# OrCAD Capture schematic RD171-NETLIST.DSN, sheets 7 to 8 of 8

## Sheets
7 2: size Custom
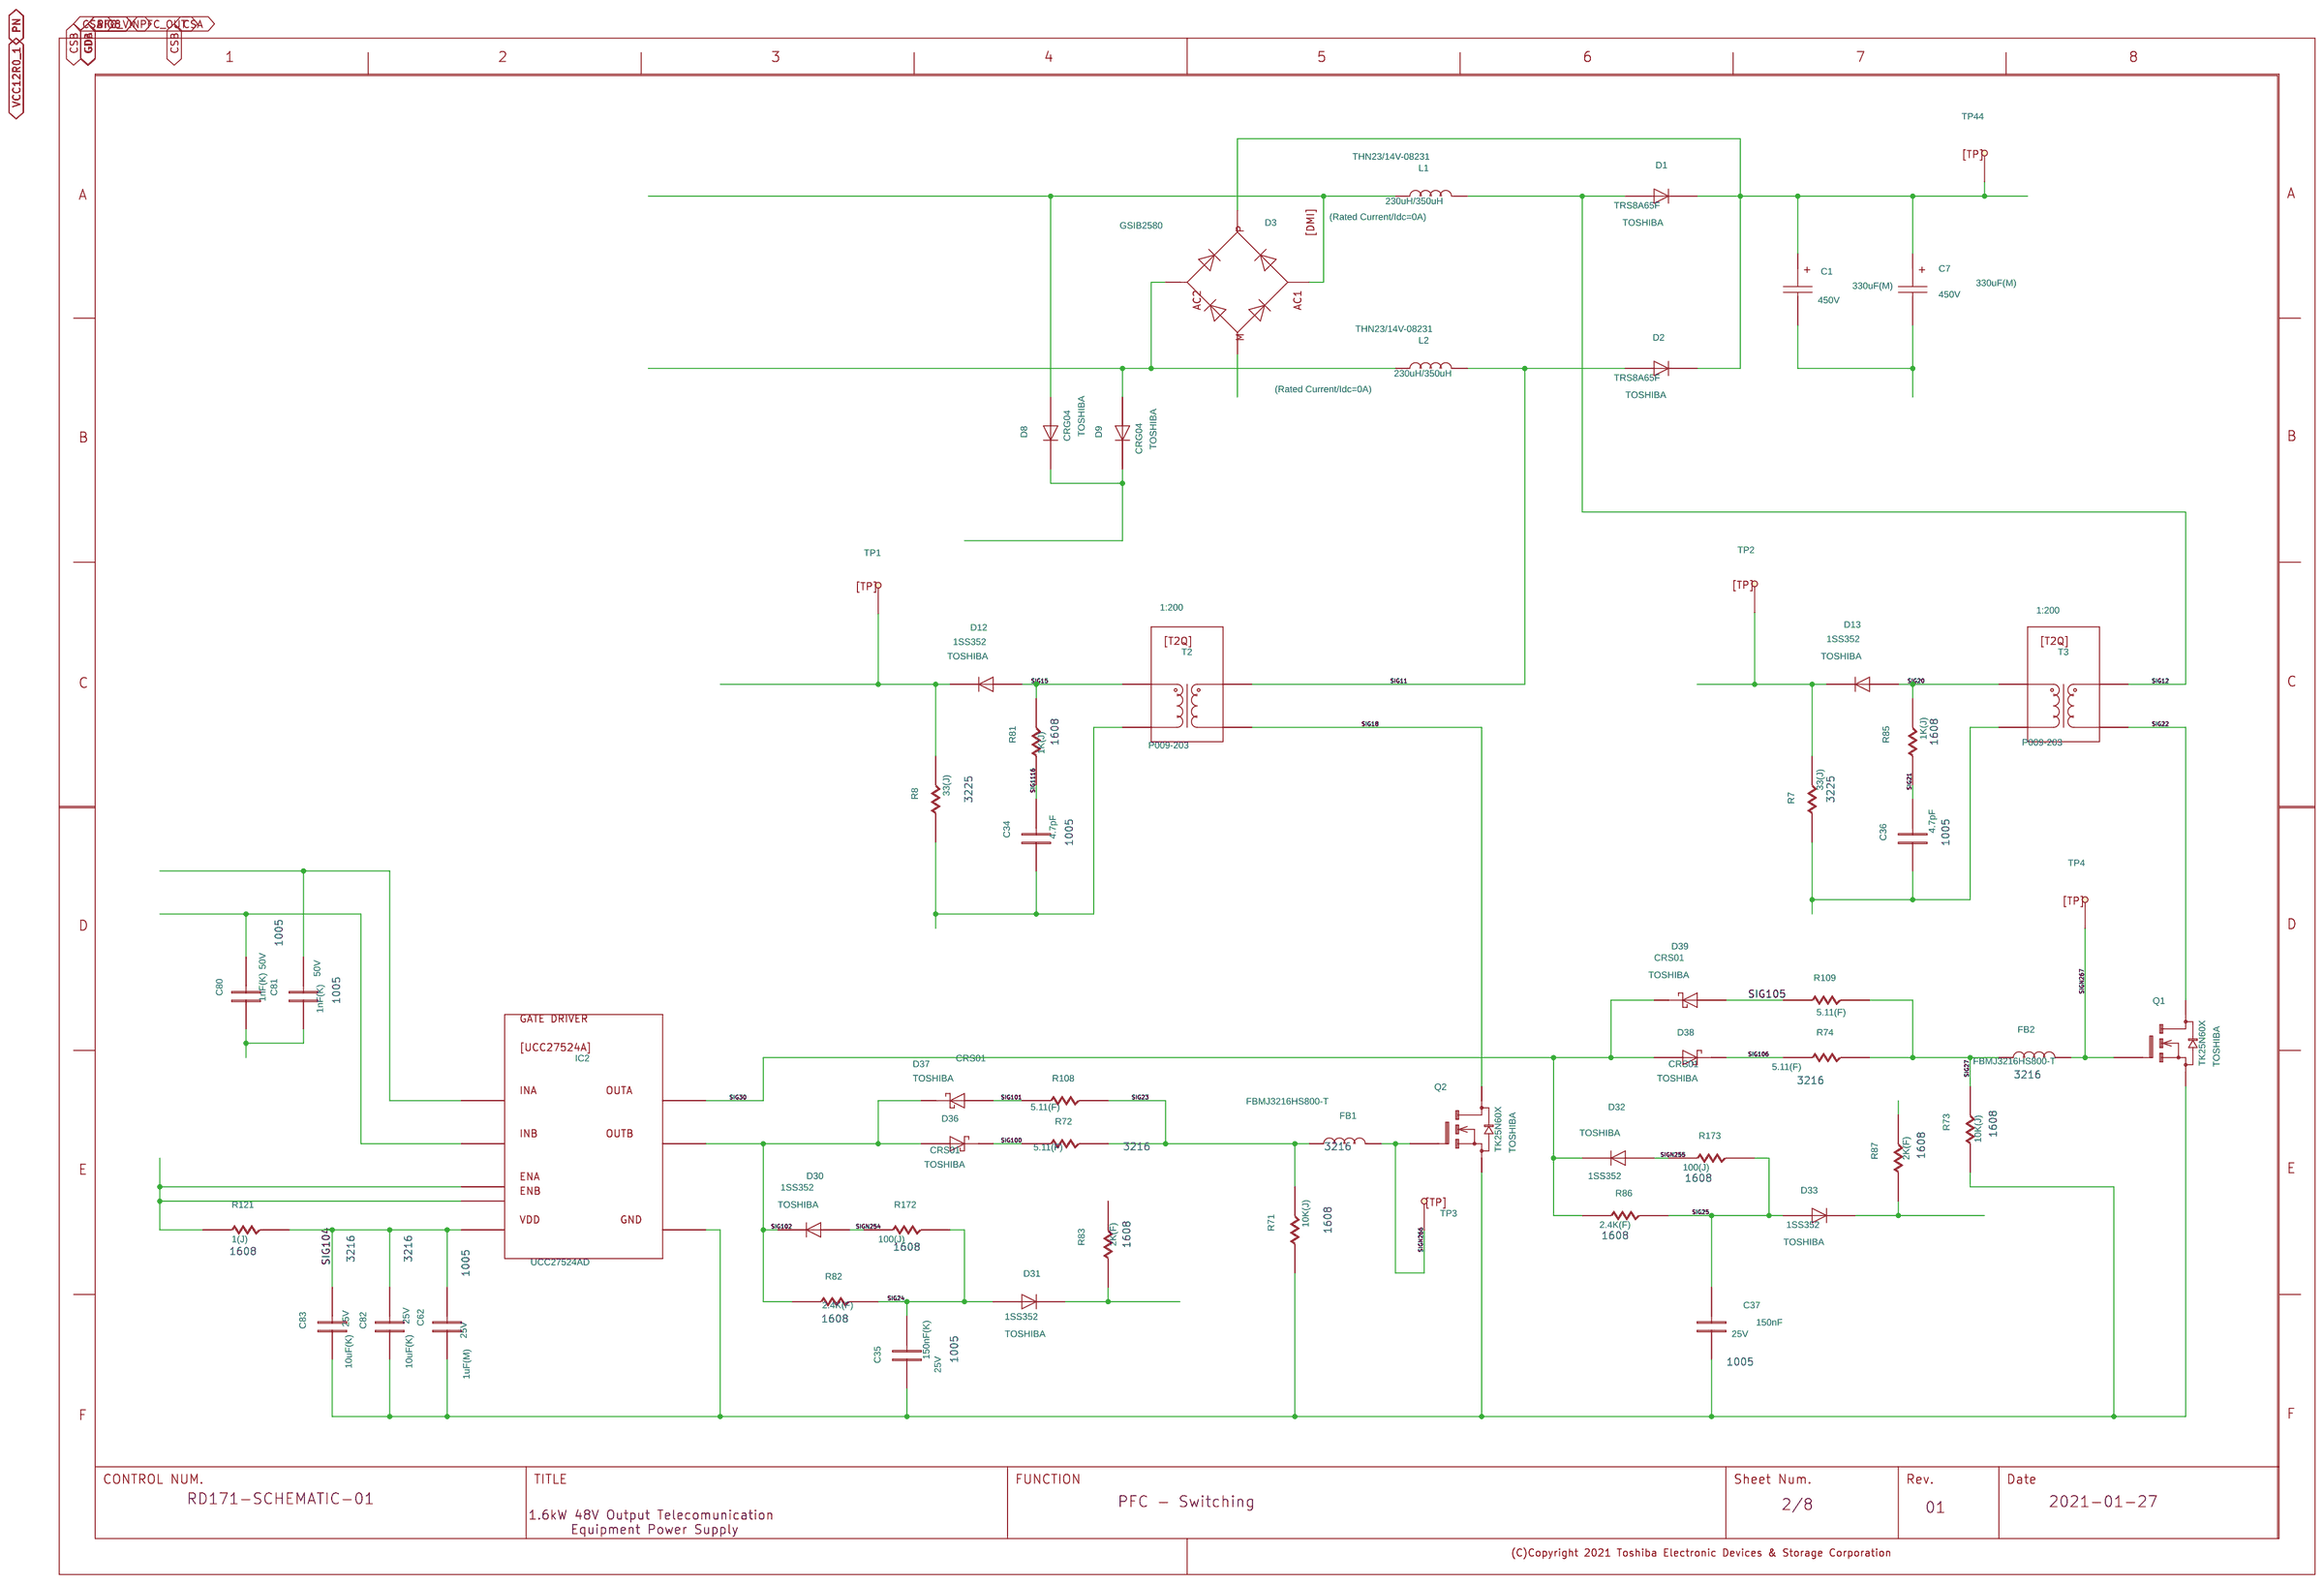
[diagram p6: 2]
8 1: size A3
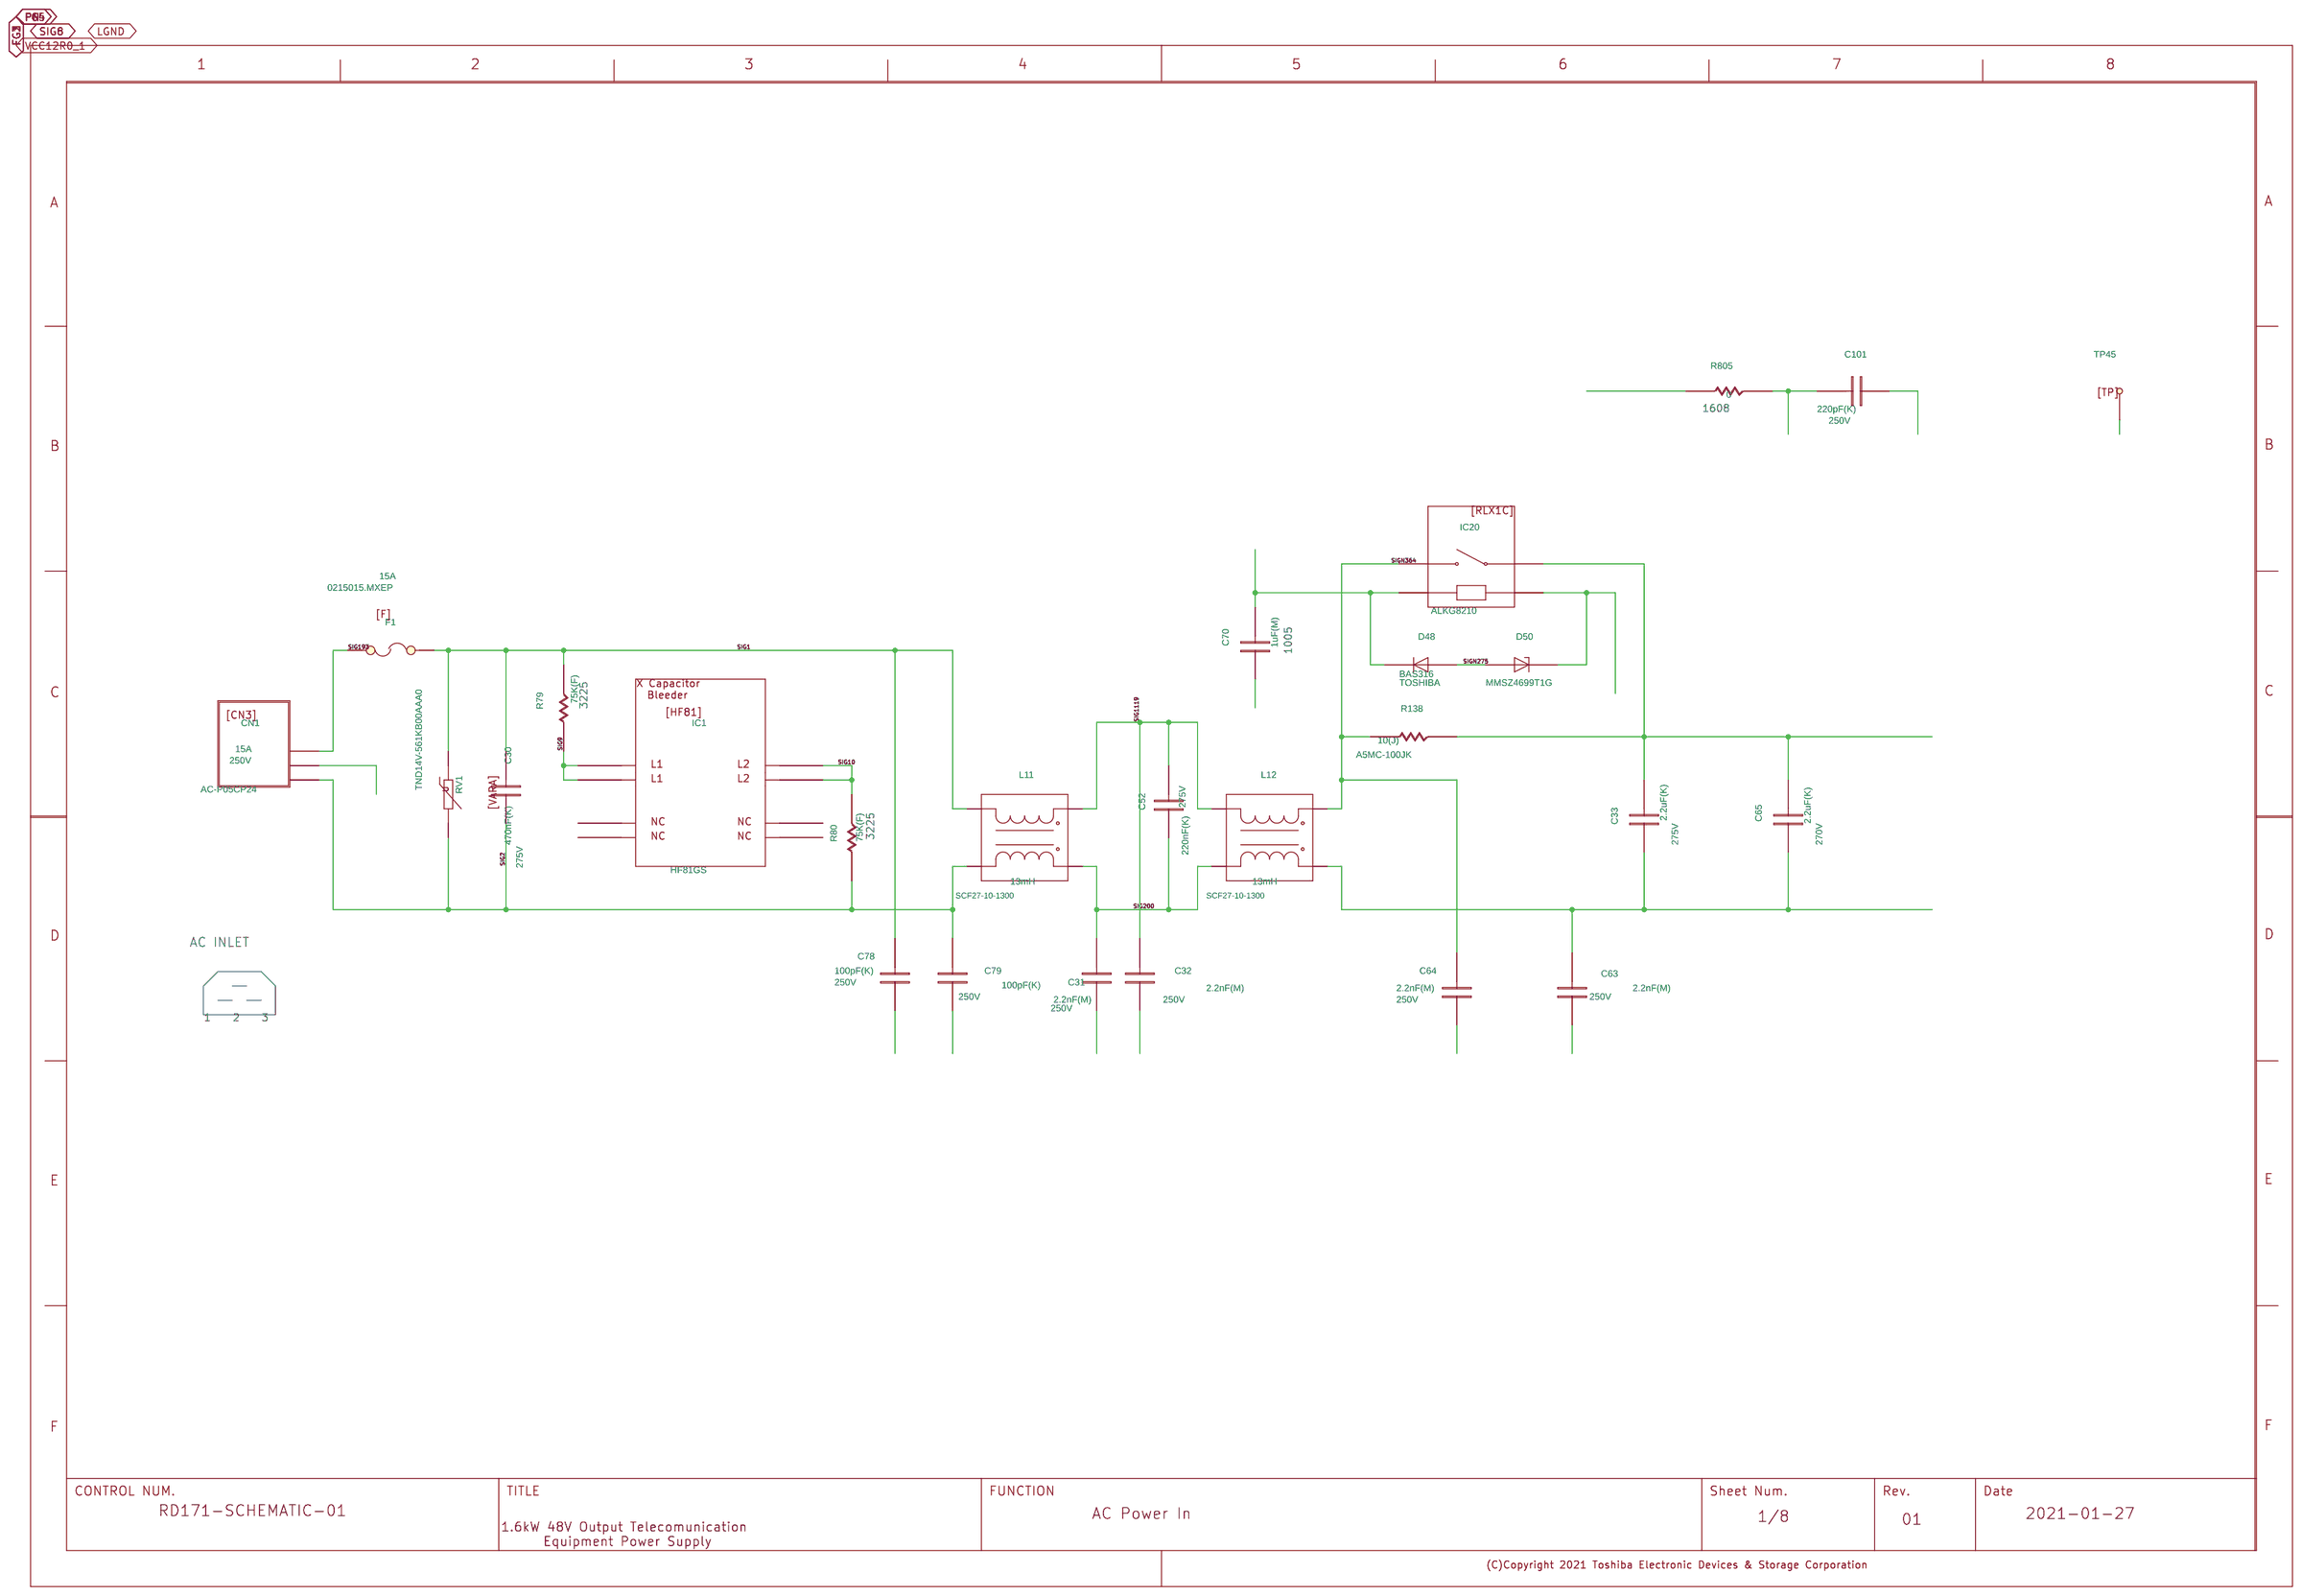
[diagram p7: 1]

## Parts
sheet 1
C30  470nF  [LE474-M]
C31  2.2nF  [DE2E3KY222MN3AM02F]
C32  2.2nF  [DE2E3KY222MN3AM02F]
C33  2.2uF  [890324026034CS]
C52  220nF  [LE224-M]
C63  2.2nF  [DE2E3KY222MN3AM02F]
C64  2.2nF  [DE2E3KY222MN3AM02F]
C65  2.2uF  [890324026034CS]
C70  1uF
C78  100pF  [DE2B3KY101KA3BM02F]
C79  100pF  [DE2B3KY101KA3BM02F]
C101  220pF  [DE2B3KY221KA3BM02F]
CN1  15A  [AC-P05CP24]
D48  D48  [BAS316]
D50  D50  [MMSZ4699T1G]
F1  15 A  [0215015.MXEP]
IC1  IC1  [HF81GS]
IC20  IC20  [ALKG8210]
L11  13mH  [SCF27-10-1300]
L12  13mH  [SCF27-10-1300]
R79  75k
R80  75k
R138  10_2.1W- FUSE  [A5MC-100JK]
R805  0
RV1  560V  [TND14V-561KB00AAA0]
TP45  TP45  [LC-22-S-WHITE]
U?#7  WAKU_DEF100
sheet 2
C1  330uF  [450MXK330MEFCSN30X30]
C7  330uF  [450MXK330MEFCSN30X30]
C34  4.7pF
C35  150nF  [C1005X5R1E154K050BC]
C36  4.7pF
C37  150nF  [C1005X5R1E154K050BC]
C62  1uF
C80  1nF
C81  1nF
C82  10uF
C83  10uF
D1  D1  [TRS8E65F]
D2  D2  [TRS8E65F]
D3  D3  [GSIB2580]
D8  D8  [CRG04]
D9  D9  [CRG04]
D12  D12  [1SS352]
D13  D13  [1SS352]
D30  D30  [1SS352]
D31  D31  [1SS352]
D32  D32  [1SS352]
D33  D33  [1SS352]
D36  D36  [CRS01]
D37  D37  [CRS01]
D38  D38  [CRS01]
D39  D39  [CRS01]
FB1  FB1  [FBMJ3216HS800-T]
FB2  FB2  [FBMJ3216HS800-T]
IC2  IC2  [UCC27524AD]
L1  230uH/350uH(RatedCurrent/Idc=0)  [THN23/14V-08231]
L2  230uH/350uH (Rated Current/Idc=0)  [THN23/14V-08231]
Q1  Q1  [TK25N60X]
Q2  Q2  [TK25N60X]
R7  33
R8  33
R71  10k
R72  5.11
R73  10k
R74  5.11
R81  1k
R82  2.4k
R83  2k
R85  1k
R86  2.4k
R87  2k
R108  5.11
R109  5.11
R121  1
R172  100
R173  100
T2  1:200  [P009-203]
T3  1:200  [P009-203]
TP1  TP1  [HK-2-S]
TP2  TP2  [HK-2-S]
TP3  TP3  [HK-2-S]
TP4  TP4  [HK-2-S]
TP44  TP44  [HK-2-S]
U?#6  WAKU_DEF100

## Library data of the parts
C30 = C: ADSMODELNAME: s_GRM32MR72A474KA01L; CAPACITANCETOLE: K; COMP: PRT_19; COMPONENTNAME: C_C.Normal_package; FUNCTION: C_C.Normal_package; GCOUNT: 1; INSTANCENAME: INS121; MAKER: OKAYA; MAXGCOUNT: 1; NOMINALCAPACITA: 470n; PARTNAME: LE474-M_OK; RATEDVOLTAGE: 100; SIZECODESMD: 3225; VAL1: 470nF(K); VAL2: 275V
C31 = C: ADSMODELNAME: s_ECKNTS222ME; CAPACITANCETOLE: M; CDMASTERCADCELG: DC0284; CHIPSIZE: [hsb`7.5mmió]; COMP: PRT_13; COMPONENTNAME: C_C.Normal_package; FNLEADFREETHET1GT2GMCTH1: N_N_N; FUNCTION: C_C.Normal_package; GCOUNT: 1; INSTANCENAME: INS259; MAKER: MURATA; MAXGCOUNT: 1; NOMINALCAPACITA: 2.2n; OUMECLASSIFICATION: ƒZƒ‰ƒ~ƒbƒNƒRƒ“ƒfƒ“ƒT; OUMEMAKER: NAE pi\jbNGNgjbNfoCX; OUMEMAKERKATAMEI: ECKNTS222ME; PARTNAME: DE2E3KY222MN3AM02F_MU; PMPRODUCTSTYPEG: ES; QUADMODEL: CON_2.2N; RATEDVOLTAGE: 250; SIZECODESMD: DIP; TEMPCHARACTERI2: E; VAL1: 2.2nF(M); VAL2: 250V
C32 = C: ADSCNVFLAG: ON; ADSMODELNAME: s_ECKNTS222ME; CAPACITANCETOLE: M; CDMASTERCADCELG: DC0284; CHIPSIZE: [hsb`7.5mmió]; COMP: PRT_13; COMPONENTNAME: C_C.Normal_package; FNLEADFREETHET1GT2GMCTH1: N_N_N; FUNCTION: C_C.Normal_package; GCOUNT: 1; ICX_PART_MODEL: CON_2.2N; INSTANCENAME: INS269; MAKER: MURATA; MAXGCOUNT: 1; NOMINALCAPACITA: 2.2n; OUMECLASSIFICATION: ƒZƒ‰ƒ~ƒbƒNƒRƒ“ƒfƒ“ƒT; OUMEMAKER: NAE pi\jbNGNgjbNfoCX; OUMEMAKERKATAMEI: ECKNTS222ME; PARTNAME: DE2E3KY222MN3AM02F_MU; PMPRODUCTSTYPEG: ES; QUADMODEL: CON_2.2N; RATEDVOLTAGE: 250; SIZECODESMD: DIP; SQ_PART_MODEL: CON_2.2N; TEMPCHARACTERI2: E; VAL1: 2.2nF(M); VAL2: 250V
C33 = C: CAPACITANCETOLE: K; CDMASTERCADCELG: DC0511; COMP: PRT_18; COMPONENTNAME: C_C.Normal_package; FNLEADFREETHET1GT2GMCTH1: 9_N_N; FUNCTION: C_C.Normal_package; GCOUNT: 1; INSTANCENAME: INS309; MAKER: Wurth; MAXGCOUNT: 1; NOMINALCAPACITA: 2.2u; OUMECLASSIFICATION: ƒtƒBƒ‹ƒƒRƒ“ƒfƒ“ƒT; OUMEMAKER: CHM “ú–{ƒPƒ~ƒRƒ“; OUMEMAKERKATAMEI: TACB2E225K; PARTNAME: 890324026034CS_WE; QUADMODEL: CON_2.2U; RATEDVOLTAGE: 250; SIZECODESMD: DIP; VAL1: 2.2uF(K); VAL2: 275V
C52 = C: CAPACITANCETOLE: M; COMP: PRT_17; COMPONENTNAME: C_C.Normal_package; FNLEADFREETHET1GT2GMCTH1: N_N_N; FUNCTION: C_C.Normal_package; GCOUNT: 1; INSTANCENAME: INS279; MAKER: OKAYA; MAXGCOUNT: 1; NOMINALCAPACITA: 220n; OUMECLASSIFICATION: ƒtƒBƒ‹ƒƒRƒ“ƒfƒ“ƒT; OUMEMAKER: NIS ƒjƒbƒZƒC“d‹@; OUMEMAKERKATAMEI: R40KI322000**M; PARTNAME: LE224-M_OK; QUADMODEL: CON_220N; RATEDVOLTAGE: 275; SIZECODESMD: DIP; VAL1: 220nF(K); VAL2: 275V
C63 = C: ADSMODELNAME: s_DE2E3KY222MN3AM02F; CAPACITANCETOLE: M; CDMASTERCADCELG: SIK0018; CHIPSIZE: [hsb`7.5mmió]; COMP: PRT_13; COMPONENTNAME: C_C.Normal_package; FNLEADFREETHET1GT2GMCTH1: N_N_N; FUNCTION: C_C.Normal_package; GCOUNT: 1; INSTANCENAME: INS289; MAKER: MURATA; MAXGCOUNT: 1; NOMINALCAPACITA: 2.2n; OUMECLASSIFICATION: ƒZƒ‰ƒ~ƒbƒNƒRƒ“ƒfƒ“ƒT; OUMEMAKER: MRT ºc»ì; PARTNAME: DE2E3KY222MN3AM02F_MU; PMPRODUCTSTYPEG: PC1; QUADMODEL: CON_2.2N; RATEDVOLTAGE: 250; SIZECODESMD: DIP; TEMPCHARACTERI2: E; VAL1: 2.2nF(M); VAL2: 250V
C64 = C: ADSMODELNAME: s_DE2E3KY222MN3AM02F; CAPACITANCETOLE: M; CDMASTERCADCELG: SIK0018; CHIPSIZE: [hsb`7.5mmió]; COMP: PRT_13; COMPONENTNAME: C_C.Normal_package; FNLEADFREETHET1GT2GMCTH1: N_N_N; FUNCTION: C_C.Normal_package; GCOUNT: 1; INSTANCENAME: INS299; MAKER: MURATA; MAXGCOUNT: 1; NOMINALCAPACITA: 2.2n; OUMECLASSIFICATION: ƒZƒ‰ƒ~ƒbƒNƒRƒ“ƒfƒ“ƒT; OUMEMAKER: MRT ºc»ì; PARTNAME: DE2E3KY222MN3AM02F_MU; PMPRODUCTSTYPEG: PC1; QUADMODEL: CON_2.2N; RATEDVOLTAGE: 250; SIZECODESMD: DIP; TEMPCHARACTERI2: E; VAL1: 2.2nF(M); VAL2: 250V
C65 = C: CAPACITANCETOLE: K; CDMASTERCADCELG: DC0511; COMP: PRT_18; COMPONENTNAME: C_C.Normal_package; FNLEADFREETHET1GT2GMCTH1: 9_N_N; FUNCTION: C_C.Normal_package; GCOUNT: 1; INSTANCENAME: INS319; MAKER: Wurth; MAXGCOUNT: 1; NOMINALCAPACITA: 2.2u; OUMECLASSIFICATION: ƒtƒBƒ‹ƒƒRƒ“ƒfƒ“ƒT; OUMEMAKER: CHM “ú–{ƒPƒ~ƒRƒ“; OUMEMAKERKATAMEI: TACB2E225K; PARTNAME: 890324026034CS_WE; QUADMODEL: CON_2.2U; RATEDVOLTAGE: 250; SIZECODESMD: DIP; VAL1: 2.2uF(K); VAL2: 270V
C70 = C: ADSMODELNAME: s_GRM155B31E105KA12D; CAPACITANCETOLE: K; CDMASTERCADCELG: KC0005; CHIPSIZE: 1005; COMP: PRT_52; COMPONENTNAME: C_C.Normal_package; FNLEADFREETHET1GT2GMCTH1: 3_0_N; FUNCTION: C_C.Normal_package; GCOUNT: 1; INSTANCENAME: INS339; MAKER: TDK; MAXGCOUNT: 1; NOMINALCAPACITA: 1u; OUMECLASSIFICATION: ƒZƒ‰ƒ~ƒbƒNƒRƒ“ƒfƒ“ƒT; OUMEMAKER: MRT ºc»ì; OUMEMAKERKATAMEI: GRM155B31E105KA12D; PARTNAME: Chip1005_GS_2; PMPRODUCTSTYPEG: HD1; QUADMODEL: CON_1U; RATEDVOLTAGE: 25; SIZECODESMD: 1005; TEMPCHARACTERI2: B; VAL1: 1uF(M); VAL2: 25V; VAL3: C1005X5R1E105M050BC
C78 = C: ADSMODELNAME: s_DE1B3KX101KA4BL01; CAPACITANCETOLE: K; CDMASTERCADCELG: RDK0051; CHIPSIZE: [hsb`7.5mmió]; COMP: PRT_29; COMPONENTNAME: C_C.Normal_package; FNLEADFREETHET1GT2GMCTH1: N_N_N; FUNCTION: C_C.Normal_package; GCOUNT: 1; INSTANCENAME: INS239; MAKER: MURATA; MAXGCOUNT: 1; NOMINALCAPACITA: 100p; OUMECLASSIFICATION: ƒZƒ‰ƒ~ƒbƒNƒRƒ“ƒfƒ“ƒT; OUMEMAKER: MRT ºc»ì; OUMEMAKERKATAMEI: DE1B3KX101KA4BL01; PARTNAME: DE2B3KY101KA3BM02F_MU; QUADMODEL: CON_100P; RATEDVOLTAGE: 250; TEMPCHARACTERI2: B; VAL1: 100pF(K); VAL2: 250V
C79 = C: ADSMODELNAME: s_DE1B3KX101KA4BL01; CAPACITANCETOLE: K; CDMASTERCADCELG: RDK0051; CHIPSIZE: [hsb`7.5mmió]; COMP: PRT_29; COMPONENTNAME: C_C.Normal_package; FNLEADFREETHET1GT2GMCTH1: N_N_N; FUNCTION: C_C.Normal_package; GCOUNT: 1; INSTANCENAME: INS249; MAKER: MURATA; MAXGCOUNT: 1; NOMINALCAPACITA: 100p; OUMECLASSIFICATION: ƒZƒ‰ƒ~ƒbƒNƒRƒ“ƒfƒ“ƒT; OUMEMAKER: MRT ºc»ì; OUMEMAKERKATAMEI: DE1B3KX101KA4BL01; PARTNAME: DE2B3KY101KA3BM02F_MU; QUADMODEL: CON_100P; RATEDVOLTAGE: 250; TEMPCHARACTERI2: B; VAL1: 100pF(K); VAL2: 250V
C101 = C: ADSMODELNAME: s_DEBB33A221KC1B; CAPACITANCETOLE: K; CDMASTERCADCELG: RD0002; COMP: PRT_50; COMPONENTNAME: C_C.Normal_package; FNLEADFREETHET1GT2GMCTH1: 9_1_N; FUNCTION: C_C.Normal_package; GCOUNT: 1; INSTANCENAME: INS329; MAKER: MURATA; MAXGCOUNT: 1; NOMINALCAPACITA: 220p; OUMECLASSIFICATION: ƒZƒ‰ƒ~ƒbƒNƒRƒ“ƒfƒ“ƒT; OUMEMAKER: MRT ºc»ì; OUMEMAKERKATAMEI: DEBB33A221KC1B; PARTNAME: DE2B3KY221KA3BM02F_MU; QUADMODEL: CON_220P; RATEDVOLTAGE: 1K; SIZECODESMD: DIP; TEMPCHARACTERI2: B; VAL1: 220pF(K); VAL2: 250V
CN1 = CN3: COMP: PRT_61; COMPONENTNAME: CN3_CN3.Normal_package; FUNCTION: CN3_CN3.Normal_package; INSTANCENAME: INS363; MAKER: ECHO ELECTRIC; PARTNAME: AC-P05CP24_ED; VAL2: 250V
D48 = D: ADSMODELNAME: s_BAS16_02W; CDMASTERCADCELG: D8101D; COMP: PRT_26; COMPONENTNAME: D_D.Normal_package; FNLEADFREETHET1GT2GMCTH1: N_N_N; FORWARDVOLTAGEM: 0; FUNCTION: D_D.Normal_package; GCOUNT: 1; INSTANCENAME: INS163; MAKER: TOSHIBA; MAXAVERAGEFORWA: 0; MAXGCOUNT: 1; MAXREPETITIVEPE: 0; MAXREVERSEVOLTA: 0; MOUNTINGFORMSMD: SMD; OUMECLASSIFICATION: »Ì¼_CI[h; OUMEMAKER: IFO CtBjIeNmW[Y; OUMEMAKERKATAMEI: BAS16-02W; PARTNAME: BAS316_TS_B; PEAKFORWARDVOLT: 0; REVERSECURRENT: 0; USERCOMPTEXT3: TOSHIBA; ZENERVOLTAGEMAX: 0; ZENERVOLTAGEMIN: 0
D50 = ZD: ADSMODELNAME: s_MMSZ4681T1G; CDMASTERCADCELG: MMK0127; COMP: PRT_47; COMPONENTNAME: ZD_ZD.Normal_package; FNLEADFREETHET1GT2GMCTH1: N_N_N; FORWARDVOLTAGEM: 0; FUNCTION: ZD_ZD.Normal_package; GCOUNT: 1; INSTANCENAME: INS153; MAKER: ON Semiconductor; MAXAVERAGEFORWA: 0; MAXGCOUNT: 1; MAXREPETITIVEPE: 0; MAXREVERSEVOLTA: 0; MOUNTINGFORMSMD: SMD; OUMECLASSIFICATION: èd³_CI[h; OUMEMAKER: ONS IZ~R_N^[; OUMEMAKERKATAMEI: MMSZ4681T1G; OUMEPARTTYPE: D; PARTNAME: MMSZ4***T*G_OS_A; PEAKFORWARDVOLT: 0; REVERSECURRENT: 0; ZENERVOLTAGEMAX: 2.52; ZENERVOLTAGEMIN: 2.28
F1 = F: COMP: PRT_21; COMPONENTNAME: F_F.Normal_package; FUNCTION: F_F.Normal_package; GCOUNT: 1; INSTANCENAME: INS109; MAKER: Littelfuse; MAXGCOUNT: 1; MOUNTINGFORMSMD: SMD; NOMINALOPERATIO: 0; PARTNAME: 02150***XEP_LF; RATEDINTERRUPTI: 0; RATEDVOLTAGE: 0; VAL1: 15A
IC1 = L81: COMP: PRT_45; COMPONENTNAME: L81_L81.Normal_package; FUNCTION: L81_L81.Normal_package; INSTANCENAME: INS131; MAKER: MPS; PARTNAME: HF81GS_MPS; SAVECOUNT: 1; UPDATEDATE: 2020/07/08; UPDATETIME: 16:40:04
IC20 = RLX1C: AUTHOR: ikeda-k; COMP: PRT_1; COMPONENTNAME: RLX1C_RLX1C.Normal_package; DATE: 2003/02/07; FUNCTION: RLX1C_RLX1C.Normal_package; INSTANCENAME: INS349; MAKER: PANASONIC; PARTNAME: ALKG*2**_PN; SAVEAREA0: -15461,-296,40419,28727; SAVECOUNT: 1; TIME: 14:49:55; UPDATEDATE: 2017/01/13; UPDATETIME: 11:13:08; UPDATEUSER: cae
L11 = HM_DLWHN6702: COMP: PRT_22; COMPONENTNAME: HM-DLWHN6702_HM-DLWHN6702.Normal_package; FUNCTION: HM-DLWHN6702_HM-DLWHN6702.Normal_package; INSTANCENAME: INS175; MAKER: NEC TOKIN; PARTNAME: SCF27-10-1300_TN; VAL2: 10A
L12 = HM_DLWHN6702: COMP: PRT_22; COMPONENTNAME: HM-DLWHN6702_HM-DLWHN6702.Normal_package; FUNCTION: HM-DLWHN6702_HM-DLWHN6702.Normal_package; INSTANCENAME: INS191; MAKER: NEC TOKIN; PARTNAME: SCF27-10-1300_TN; VAL2: 10A
R79 = R: ADSMODELNAME: s_RK73H2ETE563F; CDMASTERCADCELG: DR903A; CHIPSIZE: 3225; COMP: PRT_23; COMPONENTNAME: R_R.Normal_package; FNLEADFREETHET1GT2GMCTH1: N_N_N; FUNCTION: R_R.Normal_package; GCOUNT: 1; INSTANCENAME: INS219; MAKER: PANASONIC; MAXGCOUNT: 1; MOUNTINGFORMSMD: SMD; NOMINALRESISTAN: 56K; OUMECLASSIFICATION: \ÊÀpÅèïRí; OUMEMAKER: KOA R[A; OUMEMAKERKATAMEI: RK73H2ETE563F; PARTNAME: Chip3225_GS_1; POWERRATING: 250m; QUADMODEL: RES_56K; RESISTANCETOLER: F; SIZECODESMD: 3225; VAL1: 75K(F); VAL2: 500mW,}1%; VAL3: ERJ-14NF7502U
R80 = R: ADSMODELNAME: s_RK73H2ETE563F; CDMASTERCADCELG: DR903A; CHIPSIZE: 3225; COMP: PRT_23; COMPONENTNAME: R_R.Normal_package; FNLEADFREETHET1GT2GMCTH1: N_N_N; FUNCTION: R_R.Normal_package; GCOUNT: 1; INSTANCENAME: INS229; MAKER: PANASONIC; MAXGCOUNT: 1; MOUNTINGFORMSMD: SMD; NOMINALRESISTAN: 56K; OUMECLASSIFICATION: \ÊÀpÅèïRí; OUMEMAKER: KOA R[A; OUMEMAKERKATAMEI: RK73H2ETE563F; PARTNAME: Chip3225_GS_1; POWERRATING: 250m; QUADMODEL: RES_56K; RESISTANCETOLER: F; SIZECODESMD: 3225; VAL1: 75K(F); VAL2: 500mW,}1%; VAL3: ERJ-14NF7502U
R138 = R: CHIPSIZE: 13x9xH25.5; COMP: PRT_33; COMPONENTNAME: R_R.Normal_package; FUNCTION: R_R.Normal_package; INSTANCENAME: INS207; MAKER: TAKMAN; PARTNAME: A5MC_UC; VAL1: 10(J); VAL2: 10_2.1W-FUSE
R805 = R: ADSMODELNAME: s_RK73Z1JTTD; CDMASTERCADCELG: KCK0203; CHIPSIZE: 1608; COMP: PRT_8; COMPONENTNAME: R_R.Normal_package; FNLEADFREETHET1GT2GMCTH1: 3_2_N; FUNCTION: R_R.Normal_package; GCOUNT: 1; INSTANCENAME: INS17025352; MAKER: KOA; MAXGCOUNT: 1; MOUNTINGFORMSMD: SMD; OUMECLASSIFICATION: \ÊÀpÅèïRí; OUMEMAKER: KOA R[A; OUMEMAKERKATAMEI: RK73Z1JTTD; PARTNAME: Chip1608_GS_1; PMPRODUCTSTYPEG: DME-HD1-PC1; POWERRATING: 100m; QUADMODEL: RES_0; RESISTANCETOLER: X; SIZECODESMD: 1608; VAL2: 100mW; VAL3: RK73Z1JTTD
RV1 = VARA: CDMASTERCADCELG: KC0008; COMP: PRT_37; COMPONENTNAME: VARA_VARA.Normal_package; FNLEADFREETHET1GT2GMCTH1: N_N_N; FUNCTION: VARA_VARA.Normal_package; GCOUNT: 1; INSTANCENAME: INS99; MAKER: NIPPON CHEMICON; MAXGCOUNT: 1; MOUNTINGFORMSMD: SMD; OUMECLASSIFICATION: ƒoƒŠƒXƒ^; OUMEMAKER: TDK ‚s‚c‚j; OUMEMAKERKATAMEI: AVR-M1608C220KT6AB; OUMEPARTTYPE: RV; PARTNAME: TND14V-561_CC; RATEDVOLTAGE: 0
TP45 = TP: COMP: PRT_49; COMPONENTNAME: TP_TP.Normal_package; FUNCTION: TP_TP.Normal_package; INSTANCENAME: INS379; MAKER: MAC8; PARTNAME: LC-22_GS
U?#7 = WAKU_DEF100: DATE: 2021-01-27; DRAWINGNUMBER: RD171-SCHEMATIC-01; FUNCTION: AC Power In; REVISION: 01; SAVEAREA0: 168739,-66042,466246,90057; SAVECOUNT: 5; SHEETNUMBER: 1/8; TITLE: 1.6kW 48V Output Telecomunication / Equipment Power Supply; UPDATEDATE: 2021/01/27; UPDATETIME: 15:56:17
C1 = CP: CAPACITANCETOLE: M; CDMASTERCADCELG: DC213N; CHIPSIZE: D35xL30; COMP: PRT_4; COMPONENTNAME: CP_CP.Normal_package; FNLEADFREETHET1GT2GMCTH1: 9_N_N; FUNCTION: CP_CP.Normal_package; GCOUNT: 1; INSTANCENAME: INS1378; MAKER: RUBYCON; MAXGCOUNT: 1; NOMINALCAPACITA: 330u; OUMECLASSIFICATION: ƒAƒ‹ƒ~“d‰ðƒRƒ“ƒfƒ“ƒT; OUMEMAKER: SIT ƒ‹ƒrƒRƒ“; OUMEMAKERKATAMEI: 450MXC330M35X40; OUMEPARTTYPE: C; PARTNAME: 450MXK330MEFCSN30X30_RB; QUADMODEL: CON_330U; RATEDVOLTAGE: 450; SIZECODESMD: DIP; VAL1: 330uF(M); VAL2: 450V; VAL3: 450MXH330
C7 = CP: CAPACITANCETOLE: M; CDMASTERCADCELG: DC213N; CHIPSIZE: D35xL30; COMP: PRT_4; COMPONENTNAME: CP_CP.Normal_package; FNLEADFREETHET1GT2GMCTH1: 9_N_N; FUNCTION: CP_CP.Normal_package; GCOUNT: 1; INSTANCENAME: INS1388; MAKER: RUBYCON; MAXGCOUNT: 1; NOMINALCAPACITA: 330u; OUMECLASSIFICATION: ƒAƒ‹ƒ~“d‰ðƒRƒ“ƒfƒ“ƒT; OUMEMAKER: SIT ƒ‹ƒrƒRƒ“; OUMEMAKERKATAMEI: 450MXC330M35X40; OUMEPARTTYPE: C; PARTNAME: 450MXK330MEFCSN30X30_RB; QUADMODEL: CON_330U; RATEDVOLTAGE: 450; SIZECODESMD: DIP; VAL1: 330uF(M); VAL2: 450V; VAL3: 450MXH330
C34 = C: ADSMODELNAME: s_GRM1552C1H4R7CA01D; CDMASTERCADCELG: KC0005; CHIPSIZE: 1005; COMP: PRT_52; COMPONENTNAME: C_C.Normal_package; FNLEADFREETHET1GT2GMCTH1: N_N_N; FUNCTION: C_C.Normal_package; GCOUNT: 1; INSTANCENAME: INS1216; MAKER: MURATA; MAXGCOUNT: 1; NOMINALCAPACITA: 4.7p; OUMECLASSIFICATION: ƒZƒ‰ƒ~ƒbƒNƒRƒ“ƒfƒ“ƒT; OUMEMAKER: MRT ºc»ì; OUMEMAKERKATAMEI: GRM1552C1H4R7CA01D; PARTNAME: Chip1005_GS_2; PMPRODUCTSTYPEG: DME; QUADMODEL: CON_4.7P; RATEDVOLTAGE: 50; SIZECODESMD: 1005; TEMPCHARACTERI2: CH; VAL2: 50V,}0.1pF; VAL3: GRM1555C1H4R7BA01D
C35 = C: ADSCNVFLAG: ON; ADSCOMPONENTNAME: C_1005; ADSMODELNAME: s_GCM155R11C473KA01J; CAPACITANCETOLE: K; CDMASTERCADCELG: KC0005; CHIPSIZE: 1005; COMP: PRT_52; COMPONENTNAME: C_C.Normal_package; FNLEADFREETHET1GT2GMCTH1: N_N_N; FUNCTION: C_C.Normal_package; GCOUNT: 1; ICX_PART_MODEL: CON_47N; INSTANCENAME: INS1256; MAKER: MURATA; MAXGCOUNT: 1; NOMINALCAPACITA: 47n; OUMECLASSIFICATION: ƒZƒ‰ƒ~ƒbƒNƒRƒ“ƒfƒ“ƒT; OUMEMAKER: MRT ºc»ì; OUMEMAKERKATAMEI: GCM155R11C473KA01J; PARTNAME: Chip1005_GS_2; QUADMODEL: CON_47N; RATEDVOLTAGE: 16; SIZECODESMD: 1005; SQ_PART_MODEL: CON_47N; TEMPCHARACTERI2: R; VAL1: 150nF(K); VAL2: 25V
C36 = C: ADSMODELNAME: s_GRM1552C1H4R7CA01D; CDMASTERCADCELG: KC0005; CHIPSIZE: 1005; COMP: PRT_52; COMPONENTNAME: C_C.Normal_package; FNLEADFREETHET1GT2GMCTH1: N_N_N; FUNCTION: C_C.Normal_package; GCOUNT: 1; INSTANCENAME: INS1206; MAKER: MURATA; MAXGCOUNT: 1; NOMINALCAPACITA: 4.7p; OUMECLASSIFICATION: ƒZƒ‰ƒ~ƒbƒNƒRƒ“ƒfƒ“ƒT; OUMEMAKER: MRT ºc»ì; OUMEMAKERKATAMEI: GRM1552C1H4R7CA01D; PARTNAME: Chip1005_GS_2; PMPRODUCTSTYPEG: DME; QUADMODEL: CON_4.7P; RATEDVOLTAGE: 50; SIZECODESMD: 1005; TEMPCHARACTERI2: CH; VAL2: 50V,}0.1pF; VAL3: GRM1555C1H4R7BA01D
C37 = C: ADSMODELNAME: s_GCM155R11C473KA01J; CAPACITANCETOLE: K; CDMASTERCADCELG: KC0005; CHIPSIZE: 1005; COMP: PRT_52; COMPONENTNAME: C_C.Normal_package; FNLEADFREETHET1GT2GMCTH1: N_N_N; FUNCTION: C_C.Normal_package; GCOUNT: 1; INSTANCENAME: INS1246; MAKER: MURATA; MAXGCOUNT: 1; NOMINALCAPACITA: 47n; OUMECLASSIFICATION: ƒZƒ‰ƒ~ƒbƒNƒRƒ“ƒfƒ“ƒT; OUMEMAKER: MRT ºc»ì; OUMEMAKERKATAMEI: GCM155R11C473KA01J; PARTNAME: Chip1005_GS_2; QUADMODEL: CON_47N; RATEDVOLTAGE: 16; SIZECODESMD: 1005; TEMPCHARACTERI2: R; VAL2: 25V
C62 = C: ADSMODELNAME: s_C1005X5R1C105M050BC; CAPACITANCETOLE: M; CDMASTERCADCELG: KC0005; CHIPSIZE: 1005; COMP: PRT_52; COMPONENTNAME: C_C.Normal_package; FNLEADFREETHET1GT2GMCTH1: N_N_N; FUNCTION: C_C.Normal_package; GCOUNT: 1; INSTANCENAME: INS1418; MAKER: TDK; MAXGCOUNT: 1; NOMINALCAPACITA: 1u; OUMECLASSIFICATION: ƒZƒ‰ƒ~ƒbƒNƒRƒ“ƒfƒ“ƒT; OUMEMAKER: TDK ‚s‚c‚j; OUMEMAKERKATAMEI: C1005X5R1C105M050BC; PARTNAME: Chip1005_GS_2; QUADMODEL: CON_1U; RATEDVOLTAGE: 16; SIZECODESMD: 1005; VAL1: 1uF(M); VAL2: 25V; VAL3: C1005X5R1E105M050BC
C80 = C: ADSMODELNAME: s_UMK105BJ102KV_F; CAPACITANCETOLE: K; CDMASTERCADCELG: KC0005; CHIPSIZE: 1005; COMP: PRT_52; COMPONENTNAME: C_C.Normal_package; FNLEADFREETHET1GT2GMCTH1: 2_0_N; FUNCTION: C_C.Normal_package; GCOUNT: 1; INSTANCENAME: INS1368; MAKER: TDK; MAXGCOUNT: 1; NOMINALCAPACITA: 1n; OUMECLASSIFICATION: ƒZƒ‰ƒ~ƒbƒNƒRƒ“ƒfƒ“ƒT; OUMEMAKER: TYD ‘¾—z—U“d; OUMEMAKERKATAMEI: UMK105BJ102KV-F; PARTNAME: Chip1005_GS_2; PMPRODUCTSTYPEG: HD1-PC1; QUADMODEL: CON_1N; RATEDVOLTAGE: 50; SIZECODESMD: 1005; TEMPCHARACTERI2: B; VAL1: 1nF(K); VAL2: 50V; VAL3: UMK105BJ102KV-F
C81 = C: ADSMODELNAME: s_UMK105BJ102KV_F; CAPACITANCETOLE: K; CDMASTERCADCELG: KC0005; CHIPSIZE: 1005; COMP: PRT_52; COMPONENTNAME: C_C.Normal_package; FNLEADFREETHET1GT2GMCTH1: 2_0_N; FUNCTION: C_C.Normal_package; GCOUNT: 1; INSTANCENAME: INS1358; MAKER: TDK; MAXGCOUNT: 1; NOMINALCAPACITA: 1n; OUMECLASSIFICATION: ƒZƒ‰ƒ~ƒbƒNƒRƒ“ƒfƒ“ƒT; OUMEMAKER: TYD ‘¾—z—U“d; OUMEMAKERKATAMEI: UMK105BJ102KV-F; PARTNAME: Chip1005_GS_2; PMPRODUCTSTYPEG: HD1-PC1; QUADMODEL: CON_1N; RATEDVOLTAGE: 50; SIZECODESMD: 1005; TEMPCHARACTERI2: B; VAL1: 1nF(K); VAL2: 50V; VAL3: UMK105BJ102KV-F
C82 = C: ADSMODELNAME: s_TMK316LD106KL_T; CAPACITANCETOLE: K; CDMASTERCADCELG: KC0014; CHIPSIZE: 3216; COMP: PRT_46; COMPONENTNAME: C_C.Normal_package; FNLEADFREETHET1GT2GMCTH1: N_N_N; FUNCTION: C_C.Normal_package; GCOUNT: 1; INSTANCENAME: INS1428; MAKER: TAIYO YUDEN; MAXGCOUNT: 1; NOMINALCAPACITA: 10u; OUMECLASSIFICATION: ƒZƒ‰ƒ~ƒbƒNƒRƒ“ƒfƒ“ƒT; OUMEMAKER: TYD ‘¾—z—U“d; OUMEMAKERKATAMEI: TMK316LD106KL-T; PARTNAME: Chip3216_GS_1; QUADMODEL: CON_10U; RATEDVOLTAGE: 25; SIZECODESMD: 3216; VAL1: 10uF(K); VAL2: 25V; VAL3: TMK316BJ106KL-T
C83 = C: ADSMODELNAME: s_TMK316LD106KL_T; CAPACITANCETOLE: K; CDMASTERCADCELG: KC0014; CHIPSIZE: 3216; COMP: PRT_46; COMPONENTNAME: C_C.Normal_package; FNLEADFREETHET1GT2GMCTH1: N_N_N; FUNCTION: C_C.Normal_package; GCOUNT: 1; INSTANCENAME: INS1438; MAKER: TAIYO YUDEN; MAXGCOUNT: 1; NOMINALCAPACITA: 10u; OUMECLASSIFICATION: ƒZƒ‰ƒ~ƒbƒNƒRƒ“ƒfƒ“ƒT; OUMEMAKER: TYD ‘¾—z—U“d; OUMEMAKERKATAMEI: TMK316LD106KL-T; PARTNAME: Chip3216_GS_1; QUADMODEL: CON_10U; RATEDVOLTAGE: 25; SIZECODESMD: 3216; VAL1: 10uF(K); VAL2: 25V; VAL3: TMK316BJ106KL-T
D1 = D: ADSMODELNAME: s_1N4148; CDMASTERCADCELG: DCR071; COMP: PRT_12; COMPONENTNAME: D_D.Normal_package; FNLEADFREETHET1GT2GMCTH1: N_N_N; FORWARDVOLTAGEM: 0; FUNCTION: D_D.Normal_package; GCOUNT: 1; INSTANCENAME: INS964; MAKER: TOSHIBA; MAXAVERAGEFORWA: 0; MAXGCOUNT: 1; MAXREPETITIVEPE: 0; MAXREVERSEVOLTA: 100; MOUNTINGFORMSMD: DIP; OUMECLASSIFICATION: ¬M_CI[h; OUMEMAKER: ROH [; OUMEMAKERKATAMEI: 1N4148; PARTNAME: TRS8A65F_TS; PEAKFORWARDVOLT: 0; REVERSECURRENT: 0; USERCOMPTEXT3: TOSHIBA; VAL3: TRS8A65F; ZENERVOLTAGEMAX: 0; ZENERVOLTAGEMIN: 0
D2 = D: ADSMODELNAME: s_1N4148; CDMASTERCADCELG: DCR071; COMP: PRT_12; COMPONENTNAME: D_D.Normal_package; FNLEADFREETHET1GT2GMCTH1: N_N_N; FORWARDVOLTAGEM: 0; FUNCTION: D_D.Normal_package; GCOUNT: 1; INSTANCENAME: INS976; MAKER: TOSHIBA; MAXAVERAGEFORWA: 0; MAXGCOUNT: 1; MAXREPETITIVEPE: 0; MAXREVERSEVOLTA: 100; MOUNTINGFORMSMD: DIP; OUMECLASSIFICATION: ¬M_CI[h; OUMEMAKER: ROH [; OUMEMAKERKATAMEI: 1N4148; PARTNAME: TRS8A65F_TS; PEAKFORWARDVOLT: 0; REVERSECURRENT: 0; USERCOMPTEXT3: TOSHIBA; VAL3: TRS8A65F; ZENERVOLTAGEMAX: 0; ZENERVOLTAGEMIN: 0
D3 = DMI: ADSMODELNAME: s_D1UBA80_EMBEDED; CDMASTERCADCELG: MMK0161; COMP: PRT_53; COMPONENTNAME: DMI_DMI.Normal_package; FNLEADFREETHET1GT2GMCTH1: N_N_N; FORWARDVOLTAGEM: 0; FUNCTION: DMI_DMI.Normal_package; GCOUNT: 1; INSTANCENAME: INS1144; MAKER: VISHAY; MAXAVERAGEFORWA: 800m; MAXGCOUNT: 1; MAXREPETITIVEPE: 800; MAXREVERSEVOLTA: 0; MOUNTINGFORMSMD: SMD; OUMECLASSIFICATION: êÊ®¬fq; OUMEMAKER: SDG Vd³HÆ; OUMEMAKERKATAMEI: D1UBA80_EMBEDED; OUMEPARTTYPE: D; PARTNAME: GSIB2580_VS; PEAKFORWARDVOLT: 950m; REVERSECURRENT: 10u; ZENERVOLTAGEMAX: 0; ZENERVOLTAGEMIN: 0
D8 = D: ADSMODELNAME: s_CRG03_T5L_TEMQ_; CDMASTERCADCELG: MMK0167; COMP: PRT_24; COMPONENTNAME: D_D.Normal_package; FNLEADFREETHET1GT2GMCTH1: N_N_N; FORWARDVOLTAGEM: 0; FUNCTION: D_D.Normal_package; GCOUNT: 1; INSTANCENAME: INS1048; MAKER: TOSHIBA; MAXAVERAGEFORWA: 1; MAXGCOUNT: 1; MAXREPETITIVEPE: 400; MAXREVERSEVOLTA: 0; MOUNTINGFORMSMD: SMD; OUMECLASSIFICATION: êÊ®¬fq; OUMEMAKER: TSB “ŒŽÅ; OUMEMAKERKATAMEI: CRG03(T5L,TEMQ); PARTNAME: CRG04_TS_A; PEAKFORWARDVOLT: 1.1; PMPRODUCTSTYPEG: HD1; REVERSECURRENT: 10u; USERCOMPTEXT3: TOSHIBA; ZENERVOLTAGEMAX: 0; ZENERVOLTAGEMIN: 0
D9 = D: ADSMODELNAME: s_CRG03_T5L_TEMQ_; CDMASTERCADCELG: MMK0167; COMP: PRT_24; COMPONENTNAME: D_D.Normal_package; FNLEADFREETHET1GT2GMCTH1: N_N_N; FORWARDVOLTAGEM: 0; FUNCTION: D_D.Normal_package; GCOUNT: 1; INSTANCENAME: INS1060; MAKER: TOSHIBA; MAXAVERAGEFORWA: 1; MAXGCOUNT: 1; MAXREPETITIVEPE: 400; MAXREVERSEVOLTA: 0; MOUNTINGFORMSMD: SMD; OUMECLASSIFICATION: êÊ®¬fq; OUMEMAKER: TSB “ŒŽÅ; OUMEMAKERKATAMEI: CRG03(T5L,TEMQ); PARTNAME: CRG04_TS_A; PEAKFORWARDVOLT: 1.1; PMPRODUCTSTYPEG: HD1; REVERSECURRENT: 10u; USERCOMPTEXT3: TOSHIBA; ZENERVOLTAGEMAX: 0; ZENERVOLTAGEMIN: 0
D12 = D: ADSMODELNAME: s_1SS352_TPH3_F_1_1E1A; CDMASTERCADCELG: D81022; COMP: PRT_27; COMPONENTNAME: D_D.Normal_package; FNLEADFREETHET1GT2GMCTH1: N_N_N; FORWARDVOLTAGEM: 0; FUNCTION: D_D.Normal_package; GCOUNT: 1; INSTANCENAME: INS1072; MAKER: TOSHIBA; MAXAVERAGEFORWA: 0; MAXGCOUNT: 1; MAXREPETITIVEPE: 0; MAXREVERSEVOLTA: 80; MOUNTINGFORMSMD: SMD; OUMECLASSIFICATION: ¬M_CI[h; OUMEMAKER: TSB “ŒŽÅ; OUMEMAKERKATAMEI: 1SS352(TPH3,F)1-1E1A; PARTNAME: 1SS352_TS_A; PEAKFORWARDVOLT: 0; REVERSECURRENT: 0; USERCOMPTEXT3: TOSHIBA; ZENERVOLTAGEMAX: 0; ZENERVOLTAGEMIN: 0
D13 = D: ADSMODELNAME: s_1SS352_TPH3_F_1_1E1A; CDMASTERCADCELG: D81022; COMP: PRT_27; COMPONENTNAME: D_D.Normal_package; FNLEADFREETHET1GT2GMCTH1: N_N_N; FORWARDVOLTAGEM: 0; FUNCTION: D_D.Normal_package; GCOUNT: 1; INSTANCENAME: INS1084; MAKER: TOSHIBA; MAXAVERAGEFORWA: 0; MAXGCOUNT: 1; MAXREPETITIVEPE: 0; MAXREVERSEVOLTA: 80; MOUNTINGFORMSMD: SMD; OUMECLASSIFICATION: ¬M_CI[h; OUMEMAKER: TSB “ŒŽÅ; OUMEMAKERKATAMEI: 1SS352(TPH3,F)1-1E1A; PARTNAME: 1SS352_TS_A; PEAKFORWARDVOLT: 0; REVERSECURRENT: 0; USERCOMPTEXT3: TOSHIBA; ZENERVOLTAGEMAX: 0; ZENERVOLTAGEMIN: 0
D30 = D: ADSMODELNAME: s_1SS352_TPH3_F_1_1E1A; CDMASTERCADCELG: D81022; COMP: PRT_27; COMPONENTNAME: D_D.Normal_package; FNLEADFREETHET1GT2GMCTH1: N_N_N; FORWARDVOLTAGEM: 0; FUNCTION: D_D.Normal_package; GCOUNT: 1; INSTANCENAME: INS1096; MAKER: TOSHIBA; MAXAVERAGEFORWA: 0; MAXGCOUNT: 1; MAXREPETITIVEPE: 0; MAXREVERSEVOLTA: 80; MOUNTINGFORMSMD: SMD; OUMECLASSIFICATION: ¬M_CI[h; OUMEMAKER: TSB “ŒŽÅ; OUMEMAKERKATAMEI: 1SS352(TPH3,F)1-1E1A; PARTNAME: 1SS352_TS_A; PEAKFORWARDVOLT: 0; REVERSECURRENT: 0; USERCOMPTEXT3: TOSHIBA; ZENERVOLTAGEMAX: 0; ZENERVOLTAGEMIN: 0
D31 = D: ADSCNVFLAG: ON; ADSCOMPONENTNAME: D_D; ADSMODELNAME: s_1SS352_TPH3_F_1_1E1A; CDMASTERCADCELG: D81022; COMP: PRT_27; COMPONENTNAME: D_D.Normal_package; FNLEADFREETHET1GT2GMCTH1: N_N_N; FORWARDVOLTAGEM: 0; FUNCTION: D_D.Normal_package; GCOUNT: 1; INSTANCENAME: INS1108; MAKER: TOSHIBA; MAXAVERAGEFORWA: 0; MAXGCOUNT: 1; MAXREPETITIVEPE: 0; MAXREVERSEVOLTA: 80; MOUNTINGFORMSMD: SMD; OUMECLASSIFICATION: ¬M_CI[h; OUMEMAKER: TSB “ŒŽÅ; OUMEMAKERKATAMEI: 1SS352(TPH3,F)1-1E1A; PARTNAME: 1SS352_TS_A; PEAKFORWARDVOLT: 0; REVERSECURRENT: 0; USERCOMPTEXT3: TOSHIBA; ZENERVOLTAGEMAX: 0; ZENERVOLTAGEMIN: 0
D32 = D: ADSMODELNAME: s_1SS352_TPH3_F_1_1E1A; CDMASTERCADCELG: D81022; COMP: PRT_27; COMPONENTNAME: D_D.Normal_package; FNLEADFREETHET1GT2GMCTH1: N_N_N; FORWARDVOLTAGEM: 0; FUNCTION: D_D.Normal_package; GCOUNT: 1; INSTANCENAME: INS1120; MAKER: TOSHIBA; MAXAVERAGEFORWA: 0; MAXGCOUNT: 1; MAXREPETITIVEPE: 0; MAXREVERSEVOLTA: 80; MOUNTINGFORMSMD: SMD; OUMECLASSIFICATION: ¬M_CI[h; OUMEMAKER: TSB “ŒŽÅ; OUMEMAKERKATAMEI: 1SS352(TPH3,F)1-1E1A; PARTNAME: 1SS352_TS_A; PEAKFORWARDVOLT: 0; REVERSECURRENT: 0; USERCOMPTEXT3: TOSHIBA; ZENERVOLTAGEMAX: 0; ZENERVOLTAGEMIN: 0
D33 = D: ADSMODELNAME: s_1SS352_TPH3_F_1_1E1A; CDMASTERCADCELG: D81022; COMP: PRT_27; COMPONENTNAME: D_D.Normal_package; FNLEADFREETHET1GT2GMCTH1: N_N_N; FORWARDVOLTAGEM: 0; FUNCTION: D_D.Normal_package; GCOUNT: 1; INSTANCENAME: INS1132; MAKER: TOSHIBA; MAXAVERAGEFORWA: 0; MAXGCOUNT: 1; MAXREPETITIVEPE: 0; MAXREVERSEVOLTA: 80; MOUNTINGFORMSMD: SMD; OUMECLASSIFICATION: ¬M_CI[h; OUMEMAKER: TSB “ŒŽÅ; OUMEMAKERKATAMEI: 1SS352(TPH3,F)1-1E1A; PARTNAME: 1SS352_TS_A; PEAKFORWARDVOLT: 0; REVERSECURRENT: 0; USERCOMPTEXT3: TOSHIBA; ZENERVOLTAGEMAX: 0; ZENERVOLTAGEMIN: 0
D36 = SBD: ADSMODELNAME: s_CUS01_TE85L_Q_; CDMASTERCADCELG: MM0042; COMP: PRT_11; COMPONENTNAME: SBD_SBD.Normal_package; FNLEADFREETHET1GT2GMCTH1: 2_0_N; FORWARDVOLTAGEM: 0; FUNCTION: SBD_SBD.Normal_package; GCOUNT: 1; INSTANCENAME: INS1182; MAKER: TOSHIBA; MAXAVERAGEFORWA: 1; MAXGCOUNT: 1; MAXREPETITIVEPE: 30; MAXREVERSEVOLTA: 0; MOUNTINGFORMSMD: SMD; OUMECLASSIFICATION: ¬p®¬fq/VbgLoA_CI[h; OUMEMAKER: TSB “ŒŽÅ; OUMEMAKERKATAMEI: CUS01(TE85L,Q); OUMEPARTTYPE: D; PARTNAME: CRS01_TS_B; PEAKFORWARDVOLT: 370m; PMPRODUCTSTYPEG: PC1; REVERSECURRENT: 500u; USERCOMPTEXT3: TOSHIBA; ZENERVOLTAGEMAX: 0; ZENERVOLTAGEMIN: 0
D37 = SBD: ADSMODELNAME: s_CUS01_TE85L_Q_; CDMASTERCADCELG: MM0042; COMP: PRT_11; COMPONENTNAME: SBD_SBD.Normal_package; FNLEADFREETHET1GT2GMCTH1: 2_0_N; FORWARDVOLTAGEM: 0; FUNCTION: SBD_SBD.Normal_package; GCOUNT: 1; INSTANCENAME: INS1194; MAKER: TOSHIBA; MAXAVERAGEFORWA: 1; MAXGCOUNT: 1; MAXREPETITIVEPE: 30; MAXREVERSEVOLTA: 0; MOUNTINGFORMSMD: SMD; OUMECLASSIFICATION: ¬p®¬fq/VbgLoA_CI[h; OUMEMAKER: TSB “ŒŽÅ; OUMEMAKERKATAMEI: CUS01(TE85L,Q); OUMEPARTTYPE: D; PARTNAME: CRS01_TS_B; PEAKFORWARDVOLT: 370m; PMPRODUCTSTYPEG: PC1; REVERSECURRENT: 500u; USERCOMPTEXT3: TOSHIBA; ZENERVOLTAGEMAX: 0; ZENERVOLTAGEMIN: 0
D38 = SBD: ADSMODELNAME: s_CUS01_TE85L_Q_; CDMASTERCADCELG: MM0042; COMP: PRT_11; COMPONENTNAME: SBD_SBD.Normal_package; FNLEADFREETHET1GT2GMCTH1: 2_0_N; FORWARDVOLTAGEM: 0; FUNCTION: SBD_SBD.Normal_package; GCOUNT: 1; INSTANCENAME: INS1158; MAKER: TOSHIBA; MAXAVERAGEFORWA: 1; MAXGCOUNT: 1; MAXREPETITIVEPE: 30; MAXREVERSEVOLTA: 0; MOUNTINGFORMSMD: SMD; OUMECLASSIFICATION: ¬p®¬fq/VbgLoA_CI[h; OUMEMAKER: TSB “ŒŽÅ; OUMEMAKERKATAMEI: CUS01(TE85L,Q); OUMEPARTTYPE: D; PARTNAME: CRS01_TS_B; PEAKFORWARDVOLT: 370m; PMPRODUCTSTYPEG: PC1; REVERSECURRENT: 500u; USERCOMPTEXT3: TOSHIBA; ZENERVOLTAGEMAX: 0; ZENERVOLTAGEMIN: 0
D39 = SBD: ADSMODELNAME: s_CUS01_TE85L_Q_; CDMASTERCADCELG: MM0042; COMP: PRT_11; COMPONENTNAME: SBD_SBD.Normal_package; FNLEADFREETHET1GT2GMCTH1: 2_0_N; FORWARDVOLTAGEM: 0; FUNCTION: SBD_SBD.Normal_package; GCOUNT: 1; INSTANCENAME: INS1170; MAKER: TOSHIBA; MAXAVERAGEFORWA: 1; MAXGCOUNT: 1; MAXREPETITIVEPE: 30; MAXREVERSEVOLTA: 0; MOUNTINGFORMSMD: SMD; OUMECLASSIFICATION: ¬p®¬fq/VbgLoA_CI[h; OUMEMAKER: TSB “ŒŽÅ; OUMEMAKERKATAMEI: CUS01(TE85L,Q); OUMEPARTTYPE: D; PARTNAME: CRS01_TS_B; PEAKFORWARDVOLT: 370m; PMPRODUCTSTYPEG: PC1; REVERSECURRENT: 500u; USERCOMPTEXT3: TOSHIBA; ZENERVOLTAGEMAX: 0; ZENERVOLTAGEMIN: 0
FB1 = L: COMP: PRT_30; COMPONENTNAME: L_L.Normal_package; FUNCTION: L_L.Normal_package; INSTANCENAME: INS1316; MAKER: TAIYO YUDEN; PARTNAME: FBMH3216_TY
FB2 = L: COMP: PRT_30; COMPONENTNAME: L_L.Normal_package; FUNCTION: L_L.Normal_package; INSTANCENAME: INS1326; MAKER: TAIYO YUDEN; PARTNAME: FBMH3216_TY
IC2 = L27524: COMP: PRT_63; COMPONENTNAME: L27524_L27524.Normal_package; FUNCTION: L27524_L27524.Normal_package; INSTANCENAME: INS1336; MAKER: TEXAS; PARTNAME: UCC27524ADR_TI; SAVECOUNT: 1; UPDATEDATE: 2020/07/08; UPDATETIME: 16:40:04
L1 = L: COMP: PRT_41; COMPONENTNAME: L_L.Normal_package; FUNCTION: L_L.Normal_package; GCOUNT: 1; INDUCTANCEMAX: 0; INDUCTANCEMIN: 0; INSTANCENAME: INS936; MAKER: TMP; MAXGCOUNT: 1; MOUNTINGFORMSMD: DIP; NOMINALINDUCTA1: 100u; NOMINALINDUCTA2: K; PARTNAME: TH23/14V-08231_TP; VAL1: 230uH/350uH; VAL2: (Rated Current/Idc=0A)
L2 = L: COMP: PRT_41; COMPONENTNAME: L_L.Normal_package; FUNCTION: L_L.Normal_package; GCOUNT: 1; INDUCTANCEMAX: 0; INDUCTANCEMIN: 0; INSTANCENAME: INS950; MAKER: TMP; MAXGCOUNT: 1; MOUNTINGFORMSMD: DIP; NOMINALINDUCTA1: 100u; NOMINALINDUCTA2: K; PARTNAME: TH23/14V-08231_TP; VAL1: 230uH/350uH; VAL2: (Rated Current/Idc=0A)
Q1 = MFNF_3: COMP: PRT_31; COMPONENTNAME: MFNF_3_MFNF_3; INSTANCENAME: INS1034; MAKER: TOSHIBA; PARTNAME: TK25N60X_TS; USERCOMPTEXT3: TOSHIBA
Q2 = MFNF_3: COMP: PRT_31; COMPONENTNAME: MFNF_3_MFNF_3; INSTANCENAME: INS1004; MAKER: TOSHIBA; PARTNAME: TK25N60X_TS; USERCOMPTEXT3: TOSHIBA
R7 = R: CHIPSIZE: 3225; COMP: PRT_23; COMPONENTNAME: R_R.Normal_package; FUNCTION: R_R.Normal_package; INSTANCENAME: INS1296; MAKER: PANASONIC; PARTNAME: Chip3225_GS_1; VAL1: 33(J); VAL2: 500mW,}5%; VAL3: ERJ-14YJ330U
R8 = R: CHIPSIZE: 3225; COMP: PRT_23; COMPONENTNAME: R_R.Normal_package; FUNCTION: R_R.Normal_package; INSTANCENAME: INS1306; MAKER: PANASONIC; PARTNAME: Chip3225_GS_1; VAL1: 33(J); VAL2: 500mW,}5%; VAL3: ERJ-14YJ330U
R71 = R: ADSMODELNAME: s_RK73B1JTTD103J@@; CDMASTERCADCELG: KC0133; CHIPSIZE: 1608; COMP: PRT_8; COMPONENTNAME: R_R.Normal_package; FNLEADFREETHET1GT2GMCTH1: N_N_N; FUNCTION: R_R.Normal_package; GCOUNT: 1; INSTANCENAME: INS1478; MAKER: KOA; MAXGCOUNT: 1; MOUNTINGFORMSMD: SMD; NOMINALRESISTAN: 10K; OUMECLASSIFICATION: \ÊÀpÅèïRí; OUMEMAKER: KOA R[A; OUMEMAKERKATAMEI: RK73B1JTTD103J@@; PARTNAME: Chip1608_GS_1; POWERRATING: 100m; QUADMODEL: RES_10K; RESISTANCETOLER: J; SIZECODESMD: 1608; VAL1: 10K(J); VAL2: 100mW,}5%; VAL3: RK73B1JTTD103J
R72 = R: ADSMODELNAME: s_RK73H2BTTD6R80F; CDMASTERCADCELG: DR901A; CHIPSIZE: 3216; COMP: PRT_5; COMPONENTNAME: R_R.Normal_package; FNLEADFREETHET1GT2GMCTH1: 3_1_N; FUNCTION: R_R.Normal_package; GCOUNT: 1; INSTANCENAME: INS1458; MAKER: BOURNS; MAXGCOUNT: 1; MOUNTINGFORMSMD: SMD; NOMINALRESISTAN: 6.8; OUMECLASSIFICATION: \ÊÀpÅèïRí; OUMEMAKER: KOA R[A; OUMEMAKERKATAMEI: RK73H2BTTD6R80F; PARTNAME: Chip3216_GS_1; POWERRATING: 125m; QUADMODEL: RES_6.8; RESISTANCETOLER: F; SIZECODESMD: 3216; VAL1: 5.11(F); VAL2: 500mW,}1%; VAL3: CRM1206-FX-5R11ELF
R73 = R: ADSMODELNAME: s_RK73B1JTTD103J@@; CDMASTERCADCELG: KC0133; CHIPSIZE: 1608; COMP: PRT_8; COMPONENTNAME: R_R.Normal_package; FNLEADFREETHET1GT2GMCTH1: N_N_N; FUNCTION: R_R.Normal_package; GCOUNT: 1; INSTANCENAME: INS1518; MAKER: KOA; MAXGCOUNT: 1; MOUNTINGFORMSMD: SMD; NOMINALRESISTAN: 10K; OUMECLASSIFICATION: \ÊÀpÅèïRí; OUMEMAKER: KOA R[A; OUMEMAKERKATAMEI: RK73B1JTTD103J@@; PARTNAME: Chip1608_GS_1; POWERRATING: 100m; QUADMODEL: RES_10K; RESISTANCETOLER: J; SIZECODESMD: 1608; VAL1: 10K(J); VAL2: 100mW,}5%; VAL3: RK73B1JTTD103J
R74 = R: ADSMODELNAME: s_RK73H2BTTD6R80F; CDMASTERCADCELG: DR901A; CHIPSIZE: 3216; COMP: PRT_5; COMPONENTNAME: R_R.Normal_package; FNLEADFREETHET1GT2GMCTH1: 3_1_N; FUNCTION: R_R.Normal_package; GCOUNT: 1; INSTANCENAME: INS1488; MAKER: BOURNS; MAXGCOUNT: 1; MOUNTINGFORMSMD: SMD; NOMINALRESISTAN: 6.8; OUMECLASSIFICATION: \ÊÀpÅèïRí; OUMEMAKER: KOA R[A; OUMEMAKERKATAMEI: RK73H2BTTD6R80F; PARTNAME: Chip3216_GS_1; POWERRATING: 125m; QUADMODEL: RES_6.8; RESISTANCETOLER: F; SIZECODESMD: 3216; VAL1: 5.11(F); VAL2: 500mW,}1%; VAL3: CRM1206-FX-5R11ELF
R81 = R: ADSMODELNAME: s_RK73B1JRTTD102J; CDMASTERCADCELG: KCK0203; CHIPSIZE: 1608; COMP: PRT_8; COMPONENTNAME: R_R.Normal_package; FNLEADFREETHET1GT2GMCTH1: N_N_N; FUNCTION: R_R.Normal_package; GCOUNT: 1; INSTANCENAME: INS1398; MAKER: KOA; MAXGCOUNT: 1; MOUNTINGFORMSMD: SMD; NOMINALRESISTAN: 1K; OUMECLASSIFICATION: \ÊÀpÅèïRí; OUMEMAKER: KOA R[A; OUMEMAKERKATAMEI: RK73B1JRTTD102J; PARTNAME: Chip1608_GS_1; PMPRODUCTSTYPEG: DME; POWERRATING: 100m; QUADMODEL: RES_1K; RESISTANCETOLER: J; SIZECODESMD: 1608; VAL1: 1K(J); VAL2: 125mW,}5%; VAL3: RK73B1JTTD102J
R82 = R: ADSMODELNAME: s_RK73H1JTD1741F; CDMASTERCADCELG: KC0008; CHIPSIZE: 1608; COMP: PRT_8; COMPONENTNAME: R_R.Normal_package; FNLEADFREETHET1GT2GMCTH1: N_N_N; FUNCTION: R_R.Normal_package; GCOUNT: 1; INSTANCENAME: INS1236; MAKER: PANASONIC; MAXGCOUNT: 1; MOUNTINGFORMSMD: SMD; NOMINALRESISTAN: 1.74K; OUMECLASSIFICATION: \ÊÀpÅèïRí; OUMEMAKER: KOA R[A; OUMEMAKERKATAMEI: RK73H1JTD1741F; PARTNAME: Chip1608_GS_1; POWERRATING: 63m; QUADMODEL: RES_1.74K; RESISTANCETOLER: F; SIZECODESMD: 1608; VAL1: 2.4K(F); VAL2: 100mW,}1%; VAL3: ERJ-3EKF1781V
R83 = R: ADSMODELNAME: s_ERJ3GEYF362V; CDMASTERCADCELG: DR802R; CHIPSIZE: 1608; COMP: PRT_8; COMPONENTNAME: R_R.Normal_package; FNLEADFREETHET1GT2GMCTH1: 3_1_N; FUNCTION: R_R.Normal_package; GCOUNT: 1; INSTANCENAME: INS1448; MAKER: PANASONIC; MAXGCOUNT: 1; MOUNTINGFORMSMD: SMD; NOMINALRESISTAN: 3.6K; OUMECLASSIFICATION: \ÊÀpÅèïRí; OUMEMAKER: NAE pi\jbNGNgjbNfoCX; OUMEMAKERKATAMEI: ERJ3GEYF362V; PARTNAME: Chip1608_GS_1; POWERRATING: 63m; QUADMODEL: RES_3.6K; RESISTANCETOLER: F; SIZECODESMD: 1608; VAL1: 2K(F); VAL2: 100mW,}1%; VAL3: ERJ-3EKF3571V
R85 = R: ADSMODELNAME: s_RK73B1JRTTD102J; CDMASTERCADCELG: KCK0203; CHIPSIZE: 1608; COMP: PRT_8; COMPONENTNAME: R_R.Normal_package; FNLEADFREETHET1GT2GMCTH1: N_N_N; FUNCTION: R_R.Normal_package; GCOUNT: 1; INSTANCENAME: INS1408; MAKER: KOA; MAXGCOUNT: 1; MOUNTINGFORMSMD: SMD; NOMINALRESISTAN: 1K; OUMECLASSIFICATION: \ÊÀpÅèïRí; OUMEMAKER: KOA R[A; OUMEMAKERKATAMEI: RK73B1JRTTD102J; PARTNAME: Chip1608_GS_1; PMPRODUCTSTYPEG: DME; POWERRATING: 100m; QUADMODEL: RES_1K; RESISTANCETOLER: J; SIZECODESMD: 1608; VAL1: 1K(J); VAL2: 125mW,}5%; VAL3: RK73B1JTTD102J
R86 = R: ADSCNVFLAG: ON; ADSCOMPONENTNAME: R_1608; ADSMODELNAME: s_RK73H1JTD1741F; CDMASTERCADCELG: KC0008; CHIPSIZE: 1608; COMP: PRT_8; COMPONENTNAME: R_R.Normal_package; FNLEADFREETHET1GT2GMCTH1: N_N_N; FUNCTION: R_R.Normal_package; GCOUNT: 1; ICX_PART_MODEL: RES_1.74K; INSTANCENAME: INS1226; MAKER: PANASONIC; MAXGCOUNT: 1; MOUNTINGFORMSMD: SMD; NOMINALRESISTAN: 1.74K; OUMECLASSIFICATION: \ÊÀpÅèïRí; OUMEMAKER: KOA R[A; OUMEMAKERKATAMEI: RK73H1JTD1741F; PARTNAME: Chip1608_GS_1; POWERRATING: 63m; QUADMODEL: RES_1.74K; RESISTANCETOLER: F; SIZECODESMD: 1608; SQ_PART_MODEL: RES_1.74K; VAL1: 2.4K(F); VAL2: 100mW,}1%; VAL3: ERJ-3EKF1781V
R87 = R: ADSMODELNAME: s_ERJ3GEYF362V; CDMASTERCADCELG: DR802R; CHIPSIZE: 1608; COMP: PRT_8; COMPONENTNAME: R_R.Normal_package; FNLEADFREETHET1GT2GMCTH1: 3_1_N; FUNCTION: R_R.Normal_package; GCOUNT: 1; INSTANCENAME: INS1508; MAKER: PANASONIC; MAXGCOUNT: 1; MOUNTINGFORMSMD: SMD; NOMINALRESISTAN: 3.6K; OUMECLASSIFICATION: \ÊÀpÅèïRí; OUMEMAKER: NAE pi\jbNGNgjbNfoCX; OUMEMAKERKATAMEI: ERJ3GEYF362V; PARTNAME: Chip1608_GS_1; POWERRATING: 63m; QUADMODEL: RES_3.6K; RESISTANCETOLER: F; SIZECODESMD: 1608; VAL1: 2K(F); VAL2: 100mW,}1%; VAL3: ERJ-3EKF3571V
R108 = R: ADSMODELNAME: s_RK73H2BTTD6R80F; CDMASTERCADCELG: DR901A; CHIPSIZE: 3216; COMP: PRT_5; COMPONENTNAME: R_R.Normal_package; FNLEADFREETHET1GT2GMCTH1: 3_1_N; FUNCTION: R_R.Normal_package; GCOUNT: 1; INSTANCENAME: INS1468; MAKER: BOURNS; MAXGCOUNT: 1; MOUNTINGFORMSMD: SMD; NOMINALRESISTAN: 6.8; OUMECLASSIFICATION: \ÊÀpÅèïRí; OUMEMAKER: KOA R[A; OUMEMAKERKATAMEI: RK73H2BTTD6R80F; PARTNAME: Chip3216_GS_1; POWERRATING: 125m; QUADMODEL: RES_6.8; RESISTANCETOLER: F; SIZECODESMD: 3216; VAL1: 5.11(F); VAL2: 500mW,}1%; VAL3: CRM1206-FX-5R11ELF
R109 = R: ADSMODELNAME: s_RK73H2BTTD6R80F; CDMASTERCADCELG: DR901A; CHIPSIZE: 3216; COMP: PRT_5; COMPONENTNAME: R_R.Normal_package; FNLEADFREETHET1GT2GMCTH1: 3_1_N; FUNCTION: R_R.Normal_package; GCOUNT: 1; INSTANCENAME: INS1498; MAKER: BOURNS; MAXGCOUNT: 1; MOUNTINGFORMSMD: SMD; NOMINALRESISTAN: 6.8; OUMECLASSIFICATION: \ÊÀpÅèïRí; OUMEMAKER: KOA R[A; OUMEMAKERKATAMEI: RK73H2BTTD6R80F; PARTNAME: Chip3216_GS_1; POWERRATING: 125m; QUADMODEL: RES_6.8; RESISTANCETOLER: F; SIZECODESMD: 3216; VAL1: 5.11(F); VAL2: 500mW,}1%; VAL3: CRM1206-FX-5R11ELF
R121 = R: ADSMODELNAME: s_ERJ3GEYJ1R0V; CDMASTERCADCELG: KC0008; CHIPSIZE: 1608; COMP: PRT_8; COMPONENTNAME: R_R.Normal_package; FNLEADFREETHET1GT2GMCTH1: 2_1_N; FUNCTION: R_R.Normal_package; INSTANCENAME: INS1266; MAKER: PANASONIC; MOUNTINGFORMSMD: SMD; OUMECLASSIFICATION: \ÊÀpÅèïRí; OUMEMAKER: NAE pi\jbNGNgjbNfoCX; OUMEMAKERKATAMEI: ERJ3GEYJ1R0V; PARTNAME: Chip1608_GS_1; PMPRODUCTSTYPEG: PC1; POWERRATING: 63m; QUADMODEL: RES_1; RESISTANCETOLER: J; SIZECODESMD: 1608; VAL1: 1(J); VAL2: 100mW,}5%; VAL3: ERJ-3GEYJ1R0V
R172 = R: CHIPSIZE: 1608; COMP: PRT_8; COMPONENTNAME: R_R.Normal_package; FUNCTION: R_R.Normal_package; INSTANCENAME: INS1276; MAKER: KOA; PARTNAME: Chip1608_GS_1; VAL1: 100(J); VAL2: 125mW,}5%; VAL3: RK73B1JTTD101J
R173 = R: CHIPSIZE: 1608; COMP: PRT_8; COMPONENTNAME: R_R.Normal_package; FUNCTION: R_R.Normal_package; INSTANCENAME: INS1286; MAKER: KOA; PARTNAME: Chip1608_GS_1; VAL1: 100(J); VAL2: 125mW,}5%; VAL3: RK73B1JTTD101J
T2 = T2Q: ADSMODELNAME: s_CT332920S_46; CDMASTERCADCELG: DT0334; COMP: PRT_7; COMPONENTNAME: T2Q_T2Q.Normal_package; FNLEADFREETHET1GT2GMCTH1: N_N_N; FUNCTION: T2Q_T2Q.Normal_package; GCOUNT: 1; INPUTVOLTAGE: 99.999K; INSTANCENAME: INS988; MAINOUTPUTVOLTA: 99.999K; MAKER: PONY; MAXGCOUNT: 1; MAXRATEDCURREN1: 0; MOUNTINGFORMSMD: DIP; OUMECLASSIFICATION: “dŒ¹ƒgƒ‰ƒ“ƒX; OUMEMAKER: TDK ‚s‚c‚j; OUMEMAKERKATAMEI: CT332920S-46; OUMEPARTTYPE: T; PARTNAME: P009-203_PO; PRIMARYINDUCTAN: 0; RATEDFREQ: 0; RATEDOUTPUT: 99.999K; RATEDOUTPUTVOLT: 0
T3 = T2Q: ADSMODELNAME: s_CT332920S_46; CDMASTERCADCELG: DT0334; COMP: PRT_7; COMPONENTNAME: T2Q_T2Q.Normal_package; FNLEADFREETHET1GT2GMCTH1: N_N_N; FUNCTION: T2Q_T2Q.Normal_package; GCOUNT: 1; INPUTVOLTAGE: 99.999K; INSTANCENAME: INS1018; MAINOUTPUTVOLTA: 99.999K; MAKER: PONY; MAXGCOUNT: 1; MAXRATEDCURREN1: 0; MOUNTINGFORMSMD: DIP; OUMECLASSIFICATION: “dŒ¹ƒgƒ‰ƒ“ƒX; OUMEMAKER: TDK ‚s‚c‚j; OUMEMAKERKATAMEI: CT332920S-46; OUMEPARTTYPE: T; PARTNAME: P009-203_PO; PRIMARYINDUCTAN: 0; RATEDFREQ: 0; RATEDOUTPUT: 99.999K; RATEDOUTPUTVOLT: 0
TP1 = TP: COMP: PRT_44; COMPONENTNAME: TP_TP.Normal_package; FUNCTION: TP_TP.Normal_package; ID: CSB; INSTANCENAME: INS1528; MAKER: MAC8; PARTNAME: HK-2_M8
TP2 = TP: COMP: PRT_44; COMPONENTNAME: TP_TP.Normal_package; FUNCTION: TP_TP.Normal_package; ID: CSA; INSTANCENAME: INS1536; MAKER: MAC8; PARTNAME: HK-2_M8
TP3 = TP: COMP: PRT_44; COMPONENTNAME: TP_TP.Normal_package; FUNCTION: TP_TP.Normal_package; INSTANCENAME: INS1552; MAKER: MAC8; PARTNAME: HK-2_M8
TP4 = TP: COMP: PRT_44; COMPONENTNAME: TP_TP.Normal_package; FUNCTION: TP_TP.Normal_package; ID: Q1-G; INSTANCENAME: INS1544; MAKER: MAC8; PARTNAME: HK-2_M8
TP44 = TP: COMP: PRT_44; COMPONENTNAME: TP_TP.Normal_package; FUNCTION: TP_TP.Normal_package; ID: PFC OUT; INSTANCENAME: INS1560; MAKER: MAC8; PARTNAME: HK-2_M8
U?#6 = WAKU_DEF100: DATE: 2021-01-27; DRAWINGNUMBER: RD171-SCHEMATIC-01; FUNCTION: PFC - Switching; REVISION: 01; SAVEAREA0: 168739,-66042,466246,90057; SAVECOUNT: 5; SHEETNUMBER: 2/8; TITLE: 1.6kW 48V Output Telecomunication / Equipment Power Supply; UPDATEDATE: 2021/01/27; UPDATETIME: 15:56:17

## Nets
VCC12R0_1: C70.2 D48.C IC2.1 IC2.8 IC20.1 R83.2 R87.2 R121.1 ; also on sheet 1 5 6
CSA: D13.C D33.C R7.2 R87.1 TP2.1 ; also on sheet 6
CSB: D12.C D31.C R8.2 R83.1 TP1.1 ; also on sheet 6
FG1: CN1.2
FG2: C79.1
FG3: C32.1 C64.1 C78.1
FG4: C31.1 C63.1
FG5: C101.2 R805.2
GDA: C81.2 IC2.2 ; also on sheet 6
GDB: C80.2 IC2.4 ; also on sheet 6
LGND: R805.1 ; also on sheet 1 2 3 4 5
PFC_OUT: C1.2 C7.2 D1.C D2.C D3.1 TP44.1 ; also on sheet 1 5 6
PFC_VIN: D8.C D9.C ; also on sheet 6
PN: C1.1 C7.1 C34.1 C35.1 C36.1 C37.1 C62.1 C70.1 C80.1 C81.1 C82.1 C83.1 C101.1 D3.4 D50.C IC2.3 IC20.2 Q1.S Q2.S R7.1 R8.1 R71.1 R73.1 T2.2 T3.2 TP45.1 ; also on sheet 1 2 5 6
SIG1: C30.2 C78.2 F1.2 L11.2 R79.2 RV1.1
SIG2: C30.1 C79.2 CN1.3 L11.3 R80.1 RV1.2
SIG6: C33.1 C63.2 C65.1 D3.3 D9.A L2.1 L12.4
SIG8: C33.2 C65.2 D3.2 D8.A IC20.3 L1.1 R138.2
SIG9: IC1.2 IC1.3 R79.1
SIG10: IC1.6 IC1.7 R80.2
SIG11: D2.A L2.2 T2.4
SIG12: D1.A L1.2 T3.4
SIG15: D12.A R81.2 T2.1
SIG18: Q2.D T2.3
SIG20: D13.A R85.2 T3.1
SIG21: C36.2 R85.1
SIG22: Q1.D T3.3
SIG23: FB1.1 R71.2 R72.2 R108.2
SIG24: C35.2 D31.A R82.2 R172.2
SIG25: C37.2 D33.A R86.2 R173.2
SIG27: FB2.1 R73.2 R74.2 R109.2
SIG30: D32.C D38.A D39.C IC2.7 R86.1
SIG100: D36.C R72.1
SIG101: D37.A R108.1
SIG102: D30.C D36.A D37.C IC2.5 R82.1
SIG104: C62.2 C82.2 C83.2 IC2.6 R121.2
SIG105: D39.A R109.1
SIG106: D38.C R74.1
SIG193: CN1.1 F1.1
SIG200: C31.2 C52.1 L11.4 L12.3
SIG1116: C34.2 R81.1
SIG1119: C32.2 C52.2 L11.1 L12.2
SIGN254: D30.A R172.1
SIGN255: D32.A R173.1
SIGN266: FB1.2 Q2.G TP3.1
SIGN267: FB2.2 Q1.G TP4.1
SIGN275: D48.A D50.A
SIGN364: C64.2 IC20.4 L12.1 R138.1

Not connected (* = marked no-connect by the designer): IC1 1 4 5 8

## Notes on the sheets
sheet 7
- 1608
- 1608
- 3225
- 3225
- 1005
- 1005
- 1005
- 1005
- 3216
- 3216
- 1608
- 3216
- 3216
- 1608
- 1608
- 1608
- 1608
- 1608
- 1608
- 1608
- 3216
- 3216
- 1005
- 1608
- 1005
- 1005
sheet 8
- 1608
- 1005
- 3225
- 3225
- AC INLET
- 1
- 2
- 3
